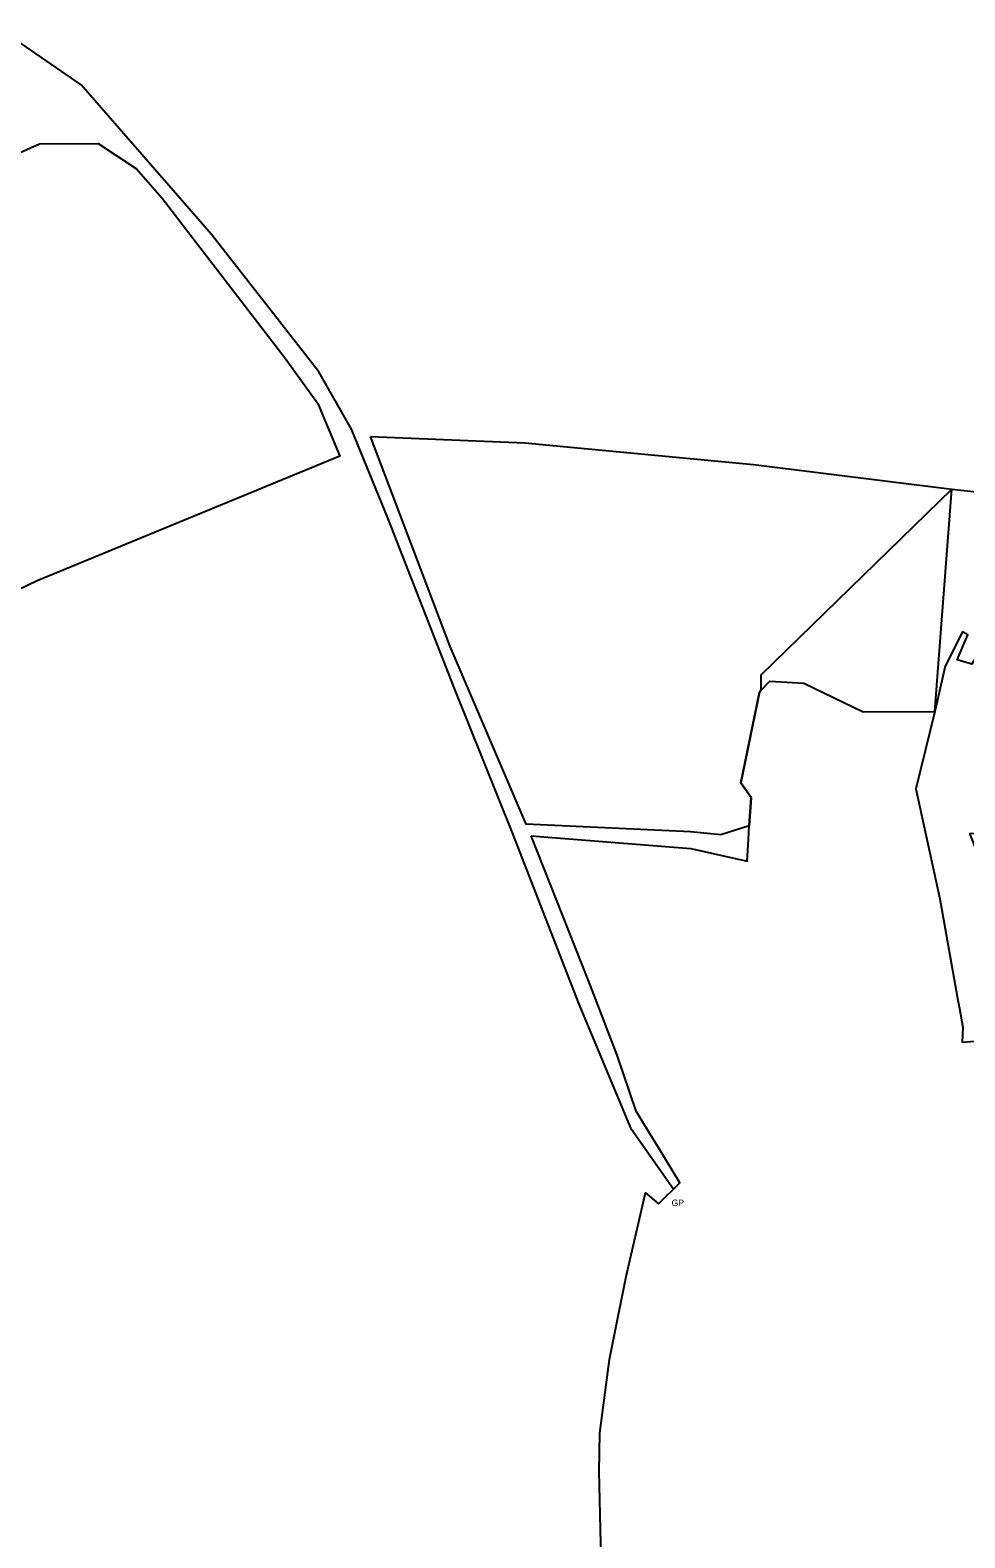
# Model space of a CAD drawing. Extents: x -615719 to -612048, y -1104937 to -1102684.
# Drawn here: x -614372 to -614082, y -1103880.3 to -1103412.3 of the extents above; entities that cross this region are included whole.
import ezdxf

# ---------------------------------------------------------------- set-up
doc = ezdxf.new("R2010")
doc.units = 0
for name, color, linetype in [('CESTY', 7, 'Continuous'), ('GRA_ZV', 7, 'Continuous'), ('OVNI_SET', 7, 'Continuous'), ('POZN', 7, 'Continuous')]:
    doc.layers.add(name, color=color, linetype=linetype)

msp = doc.modelspace()

# ---------------------------------------------------------------- linework, layer by layer
at = {"layer": 'CESTY'}
msp.add_lwpolyline([(-614172.54, -1103771.99), (-614185.4, -1103753.57), (-614201.68, -1103714.71), (-614222.32, -1103661.44), (-614240.37, -1103616.67), (-614260.9, -1103563.99), (-614272.34, -1103536.23), (-614282.43, -1103518.41), (-614315.75, -1103475.75), (-614356.17, -1103429.27), (-614380.75, -1103412.31)], dxfattribs=at)
at = {"layer": 'GRA_ZV'}
for points in [[(-614394.85, -1103459.11), (-614369.04, -1103447.64), (-614350.93, -1103447.52), (-614338.97, -1103455.39), (-614331, -1103464.52), (-614292.89, -1103514.18), (-614282.78, -1103528.17), (-614275.87, -1103544.52), (-614369.8, -1103583.22), (-614495.92, -1103644.13)], [(-614266.4, -1103538.41), (-614218.54, -1103540.43), (-614147.63, -1103547.19), (-614086.05, -1103554.8), (-614145.31, -1103612.59), (-614145.31, -1103617.35)], [(-614151.51, -1103646.01), (-614148.35, -1103650.47), (-614148.9, -1103659.35), (-614157.75, -1103662.16), (-614167.13, -1103661.15), (-614218.06, -1103658.76), (-614241.64, -1103603.66), (-614266.4, -1103538.41)], [(-614086.05, -1103554.8), (-614066.22, -1103556.93), (-614060.57, -1103557.54), (-614064.61, -1103559.48), (-614066.46, -1103562.44), (-614077.99, -1103580.96), (-614067.16, -1103588.26), (-614079.8, -1103609.17), (-614084.44, -1103607.77), (-614081.04, -1103600.03), (-614082.74, -1103599.1), (-614088.16, -1103609.79), (-614091.36, -1103623.82), (-614086.05, -1103554.8)], [(-614145.31, -1103617.35), (-614145.71, -1103617.77), (-614151.51, -1103646.01)]]:
    msp.add_lwpolyline(points, dxfattribs=at)
at = {"layer": 'OVNI_SET'}
for points in [[(-614216.57, -1103662.47), (-614167.02, -1103666.35), (-614149.58, -1103670.32), (-614149.16, -1103663.49), (-614148.9, -1103659.35), (-614148.35, -1103650.47), (-614151.51, -1103646.01), (-614145.71, -1103617.77), (-614145.31, -1103617.35), (-614142.53, -1103614.4), (-614131.97, -1103615.05), (-614113.52, -1103623.93), (-614091.36, -1103623.82)], [(-614091.36, -1103623.82), (-614097.26, -1103647.82), (-614089.82, -1103682.02), (-614084.15, -1103713.42), (-614083.68, -1103716.04), (-614082.62, -1103721.87), (-614082.86, -1103726.44), (-614080.22, -1103726.27), (-614076.72, -1103726.13), (-614076.89, -1103713.24), (-614077.06, -1103699.59), (-614077.59, -1103691.12), (-614077.77, -1103688.14), (-614072.48, -1103687.29), (-614070.05, -1103686.9), (-614078.07, -1103667.71), (-614080.51, -1103661.71), (-614033.49, -1103661.48)], [(-614177.07, -1103776.62), (-614170.42, -1103770.13), (-614176.96, -1103759.41), (-614180.13, -1103754.22), (-614183.99, -1103747.9), (-614189.86, -1103730.55), (-614196.35, -1103713.58), (-614198.85, -1103707.07), (-614216.57, -1103662.47)], [(-614188.42, -1103976.41), (-614188.01, -1103970.34), (-614191.54, -1103932.69), (-614194.32, -1103908.92), (-614195.49, -1103859.7), (-614195.24, -1103847.81), (-614192.23, -1103824.97), (-614190.77, -1103817.69), (-614187.05, -1103799.17), (-614181.08, -1103773.27), (-614177.07, -1103776.62)]]:
    msp.add_lwpolyline(points, dxfattribs=at)

# ---------------------------------------------------------------- texts
at = {"layer": 'POZN'}
msp.add_text('GP', height=2, dxfattribs=at).set_placement((-614172.99, -1103777.33))

doc.saveas('drawing.dxf')
